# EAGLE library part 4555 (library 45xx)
Dual binary 1 of 4 DECODER/DEMULTIPLEXER
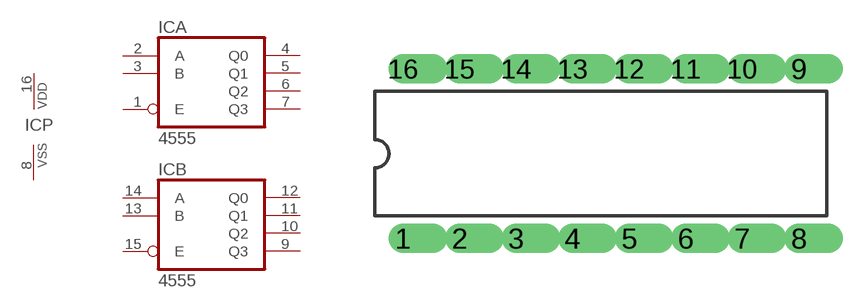
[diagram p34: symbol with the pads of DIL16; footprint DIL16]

Designator prefix IC; gates A=4555 B=4555 P=PWRN

## 4555N  [DIL16]
1  A:E  in
2  A:A  in
3  A:B  in
4  A:Q0  out
5  A:Q1  out
6  A:Q2  out
7  A:Q3  out
8  P:VSS  pwr
9  B:Q3  out
10  B:Q2  out
11  B:Q1  out
12  B:Q0  out
13  B:B  in
14  B:A  in
15  B:E  in
16  P:VDD  pwr

## Footprint DIL16 (pad centres in mm)
Dual In Line
drill 0.813 offset: 1 -8.89,-3.81; 2 -6.35,-3.81; 3 -3.81,-3.81; 4 -1.27,-3.81; 5 1.27,-3.81; 6 3.81,-3.81; 7 6.35,-3.81; 8 8.89,-3.81; 9 8.89,3.81; 10 6.35,3.81; 11 3.81,3.81; 12 1.27,3.81; 13 -1.27,3.81; 14 -3.81,3.81; 15 -6.35,3.81; 16 -8.89,3.81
